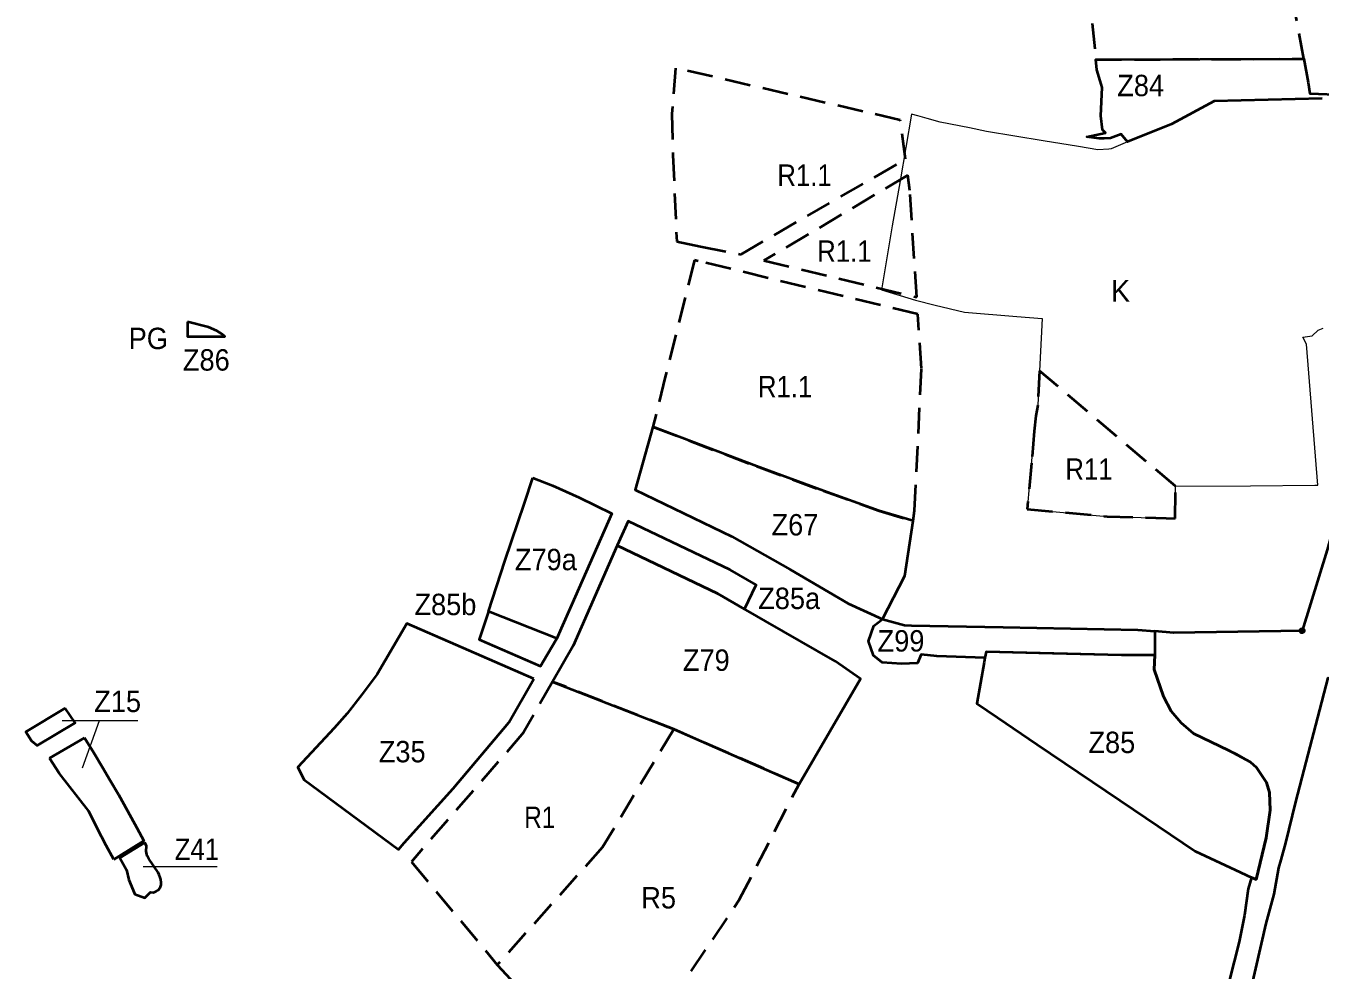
# Model space of a CAD drawing. Extents: x -650276 to -642489, y -1074311 to -1066658.
# Drawn here: x -646636 to -645184, y -1071749 to -1070690 of the extents above; entities that cross this region are included whole.
import ezdxf

# ---------------------------------------------------------------- set-up
doc = ezdxf.new("R2010")
doc.units = 0
doc.header["$LTSCALE"] = 9.6
doc.header["$PDMODE"] = 32
doc.header["$PDSIZE"] = 4.8
doc.linetypes.add('MEDIUM_DASHED', pattern=[4.5, 3, -1.5])
for name, color, linetype, lineweight in [('44', 7, 'Continuous', 40), ('45', 7, 'Continuous', 40), ('46', 7, 'Continuous', 13), ('47', 7, 'Continuous', 13), ('48', 7, 'Continuous', 13), ('60', 7, 'Continuous', 35), ('61', 7, 'MEDIUM_DASHED', 40), ('62', 7, 'Continuous', 35)]:
    doc.layers.add(name, color=color, linetype=linetype, lineweight=lineweight)

msp = doc.modelspace()

# ---------------------------------------------------------------- linework, layer by layer
at = {"layer": '44'}
msp.add_line((-645369.665, -1071395.694), (-645370.24, -1071411.83), dxfattribs=at)
for points in [[(-645182, -1070771), (-645303, -1070774), (-645351, -1070800), (-645400.05, -1070819.84), (-645407.37, -1070810.95), (-645419.18, -1070815.44), (-645426.36, -1070815.78), (-645432.07, -1070816.05), (-645445.81, -1070814.06), (-645429.993, -1070810.647), (-645424.969, -1070809.563), (-645428.39, -1070806.09), (-645430, -1070790.68), (-645428.73, -1070758.67), (-645430.84, -1070751.43), (-645434.53, -1070738.77), (-645435.711, -1070727.497), (-645202.41, -1070726.571), (-645197.539, -1070753.128), (-645195.527, -1070765.319), (-645156.988, -1070766.884)], [(-645078.23, -1070915.65), (-645092.67, -1070979.52), (-645176.14, -1071277.26), (-645204.341, -1071368.19)], [(-645407.045, -1071395.646), (-645499.65, -1071393.3), (-645558.872, -1071391.801), (-645560.11, -1071398.7), (-645614.201, -1071396.844), (-645631.44, -1071394.9), (-645635.795, -1071404.403), (-645653.742, -1071405.36), (-645675.177, -1071403.922), (-645685.098, -1071395.824), (-645690.677, -1071379.721), (-645684.785, -1071362.539), (-645674.947, -1071355.071), (-645650.28, -1071362.07), (-645642.431, -1071362.259), (-645539.738, -1071364.092)], [(-645539.738, -1071364.092), (-645388.619, -1071366.991), (-645369.696, -1071368.676)], [(-645369.67, -1071368.678), (-645369.665, -1071395.694), (-645407.045, -1071395.646)], [(-645204.341, -1071368.19), (-645348.55, -1071370.559), (-645369.67, -1071368.678)], [(-645222.48, -1071606.08), (-645211.27, -1071560.01), (-645199.61, -1071515.68), (-645186.67, -1071465.55), (-645175.06, -1071420.93), (-645167.58, -1071421.19), (-645167.37, -1071415.2), (-645163.56, -1071415.3), (-645164.76, -1071401.79), (-645166.34, -1071384.07)], [(-645560.94, -1071403.441), (-645569.07, -1071449.88), (-645545.817, -1071465.611)], [(-645370.24, -1071411.83), (-645369.665, -1071395.694), (-645407.045, -1071395.646), (-645558.872, -1071391.801), (-645560.11, -1071398.7), (-645560.94, -1071403.441)], [(-645370.24, -1071411.83), (-645359.64, -1071442), (-645351.06, -1071458.3), (-645340.16, -1071471.63), (-645326.29, -1071483.41), (-645286.62, -1071502.67), (-645278.52, -1071506.12)], [(-645326.29, -1071483.41), (-645340.16, -1071471.63), (-645351.06, -1071458.3), (-645359.64, -1071442), (-645370.24, -1071411.83)], [(-645545.817, -1071465.611), (-645501.37, -1071495.68), (-645393.34, -1071568.75)], [(-645279.531, -1071636.404), (-645261.094, -1071645.025), (-645256.02, -1071647.398), (-645244.81, -1071600.61), (-645240.26, -1071569.52), (-645240.82, -1071549.6), (-645244.4, -1071538.48), (-645255.51, -1071521.55), (-645262.36, -1071515.72), (-645286.62, -1071502.67), (-645326.29, -1071483.41)], [(-645278.52, -1071506.12), (-645262.36, -1071515.72), (-645255.51, -1071521.55), (-645244.4, -1071538.48), (-645240.82, -1071549.6), (-645240.26, -1071569.52), (-645244.81, -1071600.61), (-645256.02, -1071647.398), (-645261.094, -1071645.025)], [(-645393.34, -1071568.75), (-645324.17, -1071615.53), (-645279.531, -1071636.404)], [(-645347.551, -1072443.527), (-645347.677, -1072391.355), (-645346.62, -1072330.914), (-645343.458, -1072278.998), (-645339.908, -1072235.158), (-645335.367, -1072185.207), (-645325.498, -1072102.789), (-645309.01, -1071998.147), (-645285.617, -1071875.733), (-645244.798, -1071696.585), (-645235.793, -1071663.703), (-645230.436, -1071634.261), (-645227.905, -1071625.277), (-645222.48, -1071606.08)], [(-645261.094, -1071645.025), (-645264.841, -1071657.687), (-645269.077, -1071687.396), (-645274.868, -1071717.176), (-645286.175, -1071761.228), (-645300.076, -1071820.179), (-645313.153, -1071883.081)]]:
    msp.add_lwpolyline(points, dxfattribs=at)
for points in [[(-646454.59, -1071021.54), (-646454.59, -1071038), (-646412.54, -1071038.01), (-646415.61, -1071035.4), (-646421.58, -1071031.81), (-646430.91, -1071027.44)], [(-645829.706, -1071343.963), (-645816.714, -1071316.828), (-645846, -1071300), (-645960.34, -1071245.09), (-645972.422, -1071272.568), (-645859.986, -1071326.563)], [(-646117.031, -1071346.48), (-646127.301, -1071378.036), (-646058.719, -1071407.796), (-646051.148, -1071395.208), (-646040.084, -1071376.813)]]:
    msp.add_lwpolyline(points, close=True, dxfattribs=at)
msp.add_point((-645204.341, -1071368.19), dxfattribs=at)
at = {"layer": '45'}
msp.add_line((-646609.21, -1071510.98), (-646570, -1071488.38), dxfattribs=at)
msp.add_line((-646609.21, -1071510.98), (-646570, -1071488.38), dxfattribs=at)
for points in [[(-645674.947, -1071355.071), (-645650.09, -1071306.433), (-645640.737, -1071244.963), (-645678.86, -1071233.58), (-645741.09, -1071211.36), (-645816.47, -1071183.63), (-645932.502, -1071139.426), (-645952.419, -1071210.117), (-645844.079, -1071262.487), (-645778.69, -1071299.362), (-645713.428, -1071337.765)], [(-646067.097, -1071196.699), (-646044.944, -1071205.157), (-646015.387, -1071218.854), (-645978.403, -1071236.481), (-646023.652, -1071339.428), (-646035.241, -1071365.795), (-646040.084, -1071376.813), (-646117.031, -1071346.48), (-646098.66, -1071290.03), (-646076.713, -1071225.138)], [(-645768.62, -1071540.17), (-645699.825, -1071422.134), (-645728.054, -1071402.382), (-645806.036, -1071357.564), (-645859.986, -1071326.563), (-645972.422, -1071272.568), (-646022.073, -1071385.273), (-646044.948, -1071425.333), (-645909.13, -1071478.56)], [(-645768.62, -1071540.17), (-645699.825, -1071422.134), (-645728.054, -1071402.382), (-645806.036, -1071357.564), (-645859.986, -1071326.563), (-645972.422, -1071272.568), (-646022.073, -1071385.273), (-646044.948, -1071425.333), (-645909.13, -1071478.56)], [(-646066.165, -1071422.155), (-646153.5, -1071383.85), (-646208.577, -1071360.044), (-646241.68, -1071416.887), (-646258.487, -1071439.265), (-646275.615, -1071460.886), (-646289.976, -1071477.514), (-646330.914, -1071521.11), (-646324, -1071535), (-646217.978, -1071613.552), (-646211.407, -1071606.247), (-646156.471, -1071545.166), (-646094.063, -1071471.007)], [(-646066.165, -1071422.155), (-646153.5, -1071383.85), (-646208.577, -1071360.044), (-646241.68, -1071416.887), (-646258.487, -1071439.265), (-646275.615, -1071460.886), (-646289.976, -1071477.514), (-646330.914, -1071521.11), (-646324, -1071535), (-646217.978, -1071613.552), (-646211.407, -1071606.247), (-646156.471, -1071545.166), (-646094.063, -1071471.007)], [(-646591.65, -1071454.91), (-646635.79, -1071481.6), (-646629.37, -1071491.74), (-646623.18, -1071496.99), (-646580.58, -1071471.48)], [(-646591.65, -1071454.91), (-646635.79, -1071481.6), (-646629.37, -1071491.74), (-646623.18, -1071496.99), (-646580.58, -1071471.48)], [(-646502.39, -1071605.72), (-646530.27, -1071622.79), (-646522.99, -1071636.22), (-646520.32, -1071647.59), (-646513.43, -1071663.64), (-646502.53, -1071667.82), (-646496.06, -1071661.5), (-646492.89, -1071661.75), (-646490.07, -1071660.88), (-646487.36, -1071659.1), (-646485.29, -1071656.53), (-646484.15, -1071653.38), (-646483.97, -1071650.63), (-646484.38, -1071647.41), (-646485.2, -1071644.85), (-646486.31, -1071641.97), (-646487.56, -1071639.23), (-646497.83, -1071624.02), (-646499.829, -1071620.704), (-646500.289, -1071619.291), (-646500.83, -1071615.62), (-646500.34, -1071609.66)], [(-646502.39, -1071605.72), (-646530.27, -1071622.79), (-646522.99, -1071636.22), (-646520.32, -1071647.59), (-646513.43, -1071663.64), (-646502.53, -1071667.82), (-646496.06, -1071661.5), (-646492.89, -1071661.75), (-646490.07, -1071660.88), (-646487.36, -1071659.1), (-646485.29, -1071656.53), (-646484.15, -1071653.38), (-646483.97, -1071650.63), (-646484.38, -1071647.41), (-646485.2, -1071644.85), (-646486.31, -1071641.97), (-646487.56, -1071639.23), (-646497.83, -1071624.02), (-646499.829, -1071620.704), (-646500.289, -1071619.291), (-646500.83, -1071615.62), (-646500.34, -1071609.66)]]:
    msp.add_lwpolyline(points, close=True, dxfattribs=at)
for points in [[(-646570, -1071488.38), (-646559.53, -1071505.12), (-646550.23, -1071520.88), (-646541.14, -1071536.3), (-646532.04, -1071551.72), (-646521.8, -1071570.34), (-646511.47, -1071589.11), (-646503.31, -1071603.95), (-646531.2, -1071621.07), (-646537.28, -1071624.8)], [(-646570, -1071488.38), (-646559.53, -1071505.12), (-646550.23, -1071520.88), (-646541.14, -1071536.3), (-646532.04, -1071551.72), (-646521.8, -1071570.34), (-646511.47, -1071589.11), (-646503.31, -1071603.95), (-646531.2, -1071621.07), (-646537.28, -1071624.8)], [(-646537.28, -1071624.8), (-646545.89, -1071609.07), (-646555.78, -1071589.66), (-646565.17, -1071570.4), (-646598.63, -1071527.8), (-646609.21, -1071510.98)], [(-646537.28, -1071624.8), (-646545.89, -1071609.07), (-646555.78, -1071589.66), (-646565.17, -1071570.4), (-646598.63, -1071527.8), (-646609.21, -1071510.98)]]:
    msp.add_lwpolyline(points, dxfattribs=at)
at = {"layer": '46'}
for p, q in [((-646510.087, -1071469.269), (-646595.257, -1071469.269)), ((-646510.087, -1071469.269), (-646595.257, -1071469.269)), ((-646421.181, -1071633.007), (-646504.11, -1071633.007)), ((-646421.181, -1071633.007), (-646504.11, -1071633.007))]:
    msp.add_line(p, q, dxfattribs=at)
msp.add_lwpolyline([(-646510.087, -1071469.269), (-646553.419, -1071469.269), (-646572.844, -1071522.353)], dxfattribs=at)
msp.add_lwpolyline([(-646510.087, -1071469.269), (-646553.419, -1071469.269), (-646572.844, -1071522.353)], dxfattribs=at)
at = {"layer": '47'}
msp.add_lwpolyline([(-645182, -1070771), (-645194.206, -1070771.303), (-645303, -1070774), (-645194.206, -1070771.303), (-645303, -1070774), (-645303, -1070774), (-645303, -1070774), (-645303, -1070774), (-645303, -1070774), (-645303, -1070774), (-645303, -1070774), (-645351, -1070800), (-645400.05, -1070819.84), (-645418.67, -1070827.72), (-645421.09, -1070827.89), (-645433.49, -1070828.76), (-645455.184, -1070825.042), (-645494.82, -1070818.45), (-645558.3, -1070808), (-645577.54, -1070804.13), (-645610.25, -1070797.55), (-645625, -1070793.5), (-645635.482, -1070790.628), (-645642.52, -1070788.7), (-645655.293, -1070863.28), (-645663.99, -1070914.06), (-645676.292, -1070985.89), (-645637.94, -1070997.4), (-645615.899, -1071002.753), (-645583.18, -1071010.7), (-645524.165, -1071015.506), (-645495.87, -1071017.81), (-645498.931, -1071076.631), (-645500.94, -1071115.24), (-645504.79, -1071144.18), (-645512.84, -1071231.9), (-645423.08, -1071239.85), (-645346.67, -1071242.07), (-645346.31, -1071206.07), (-645262.13, -1071205.432), (-645189.902, -1071204.885), (-645186.64, -1071204.86), (-645199.57, -1071046.58), (-645203.66, -1071038.81), (-645193.24, -1071037.31), (-645186.18, -1071030.83), (-645180.72, -1071028.86)], dxfattribs=at)
at = {"layer": '61'}
msp.add_line((-645909.13, -1071478.56), (-646044.948, -1071425.333), dxfattribs=at)
for points in [[(-645444.47, -1070643.85), (-645435.711, -1070727.497), (-645301.722, -1070726.965), (-645202.41, -1070726.571), (-645221.272, -1070623.729)], [(-646044.948, -1071425.333), (-646077.593, -1071482.499), (-646203.387, -1071627.322), (-646107, -1071743)]]:
    msp.add_lwpolyline(points, dxfattribs=at)
for points in [[(-645905.795, -1070931.641), (-645879, -1070937), (-645834, -1070946), (-645649.136, -1070839.223), (-645655.04, -1070795.257), (-645907.061, -1070736.979), (-645911.345, -1070788.463), (-645910.048, -1070834.649)], [(-645646.718, -1070857.232), (-645808, -1070953), (-645636.529, -1070993.874), (-645644.425, -1070874.306)], [(-645881.661, -1070953.494), (-645885.966, -1070952.452), (-645918.57, -1071083.449), (-645932.502, -1071139.426), (-645816.47, -1071183.63), (-645741.09, -1071211.36), (-645678.86, -1071233.58), (-645640.737, -1071244.963), (-645638.935, -1071233.122), (-645631.241, -1071073.956), (-645635.256, -1071013.15)], [(-645512.84, -1071231.9), (-645423.08, -1071239.85), (-645356.794, -1071241.776), (-645346.67, -1071242.07), (-645346.31, -1071206.07), (-645498.931, -1071076.631), (-645500.94, -1071115.24), (-645503.08, -1071126.98), (-645504.79, -1071144.18), (-645507.84, -1071180.326)], [(-645909.13, -1071478.56), (-645989, -1071611), (-646107, -1071743), (-645987.026, -1071872.902), (-645913.616, -1071786.041), (-645835.644, -1071670.191), (-645768.62, -1071540.17)]]:
    msp.add_lwpolyline(points, close=True, dxfattribs=at)

# ---------------------------------------------------------------- texts
at = {"layer": '44', "width": 0.95}
for s, p in [('Z84', (-645411.663, -1070768.505)), ('Z84', (-645411.663, -1070768.505)), ('Z86', (-646459.658, -1071076.35)), ('Z86', (-646459.658, -1071076.35)), ('Z85b', (-646199.969, -1071350.698)), ('Z85a', (-645814.405, -1071343.847)), ('Z85a', (-645814.405, -1071343.847)), ('Z99', (-645680.485, -1071391.504)), ('Z99', (-645680.485, -1071391.504)), ('Z85', (-645444.048, -1071505.433)), ('Z85', (-645444.048, -1071505.433))]:
    msp.add_text(s, height=24, dxfattribs=at).set_placement(p)
at = {"layer": '46'}
for s, width, p in [('Z67', 0.95, (-645799.458, -1071261.304)), ('Z67', 0.95, (-645799.458, -1071261.304)), ('Z79a', 0.95, (-646087.322, -1071300.282)), ('Z79', 0.95, (-645898.897, -1071413.165)), ('Z79', 0.95, (-645898.897, -1071413.165)), ('Z15', 0.95, (-646559.155, -1071459.428)), ('Z15', 0.95, (-646559.155, -1071459.428)), ('Z35', 0.95, (-646239.99, -1071515.768)), ('Z35', 0.95, (-646239.99, -1071515.768)), ('Z41', 0.9, (-646468.869, -1071625.297)), ('Z41', 0.9, (-646468.869, -1071625.297))]:
    msp.add_text(s, height=24, dxfattribs=dict(at, width=width)).set_placement(p)
at = {"layer": '48'}
msp.add_text('K', height=24, dxfattribs=at).set_placement((-645418.824, -1070998.868))
msp.add_text('K', height=24, dxfattribs=at).set_placement((-645418.824, -1070998.868))
at = {"layer": '60', "width": 0.95}
msp.add_text('PG', height=24, dxfattribs=at).set_placement((-646520.539, -1071052.252))
msp.add_text('PG', height=24, dxfattribs=at).set_placement((-646520.539, -1071052.252))
at = {"layer": '62'}
for s, width, p in [('R1.1', 0.9, (-645792.947, -1070869.095)), ('R1.1', 0.9, (-645748.253, -1070954.32)), ('R1.1', 0.9, (-645814.758, -1071106.298)), ('R11', 0.9, (-645469.881, -1071198.853)), ('R1', 0.85, (-646076.842, -1071589.396)), ('R5', 0.95, (-645945.557, -1071679.725)), ('R5', 0.95, (-645945.557, -1071679.725))]:
    msp.add_text(s, height=24, dxfattribs=dict(at, width=width)).set_placement(p)

doc.saveas('drawing.dxf')
